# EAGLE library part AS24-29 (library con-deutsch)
DEUTSCH Connector
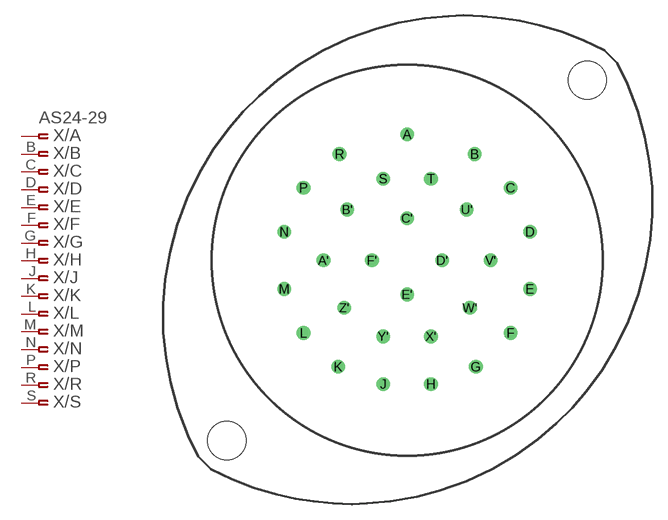
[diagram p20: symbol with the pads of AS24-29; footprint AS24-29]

Designator prefix X; gates /A=PINF_VAL /B=ASPINF /C=ASPINF /D=ASPINF /E=ASPINF /F=ASPINF /G=ASPINF /H=ASPINF /J=ASPINF /K=ASPINF /L=ASPINF /M=ASPINF /N=ASPINF /P=ASPINF /R=ASPINF /S=ASPINF /T=ASPINF /A'=PINF_VAL /B'=ASPINF /C'=ASPINF /D'=ASPINF /E'=ASPINF /F'=ASPINF /U'=ASPINF /V'=ASPINF /W'=ASPINF /X'=ASPINF /Y'=ASPINF /Z'=ASPINF

## AS24-29 (OC_FARNELL: unknown; OC_NEWARK: unknown)  [AS24-29]
A  /A:1  pas
A'  /A':1  pas
B  /B:1  pas
B'  /B':1  pas
C  /C:1  pas
C'  /C':1  pas
D  /D:1  pas
D'  /D':1  pas
E  /E:1  pas
E'  /E':1  pas
F  /F:1  pas
F'  /F':1  pas
G  /G:1  pas
H  /H:1  pas
J  /J:1  pas
K  /K:1  pas
L  /L:1  pas
M  /M:1  pas
N  /N:1  pas
P  /P:1  pas
R  /R:1  pas
S  /S:1  pas
T  /T:1  pas
U'  /U':1  pas
V'  /V':1  pas
W'  /W':1  pas
X'  /X':1  pas
Y'  /Y':1  pas
Z'  /Z':1  pas

## Footprint AS24-29 (pad centres in mm)
DEUTSCH Connector
drill 0.813 round: A 0,12.217; A' -8.103,0; B 6.553,10.312; B' -5.791,4.928; C 10.033,7.036; C' 0,4.089; D 11.913,2.769; D' 3.404,0; E 11.913,-2.769; E' 0,-3.302; F 10.033,-7.036; F' -3.404,0; G 6.68,-10.312; H 2.311,-11.989; J -2.311,-11.989; K -6.68,-10.312; L -10.033,-7.036; M -11.913,-2.769; N -11.913,2.769; P -10.033,7.036; R -6.553,10.312; S -2.311,7.925; T 2.311,7.925; U' 5.791,4.928; V' 8.103,0; W' 6.096,-4.597; X' 2.311,-7.366; Y' -2.311,-7.366; Z' -6.096,-4.597
hole 3.7 at -17.462,-17.462
hole 3.7 at 17.462,17.462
